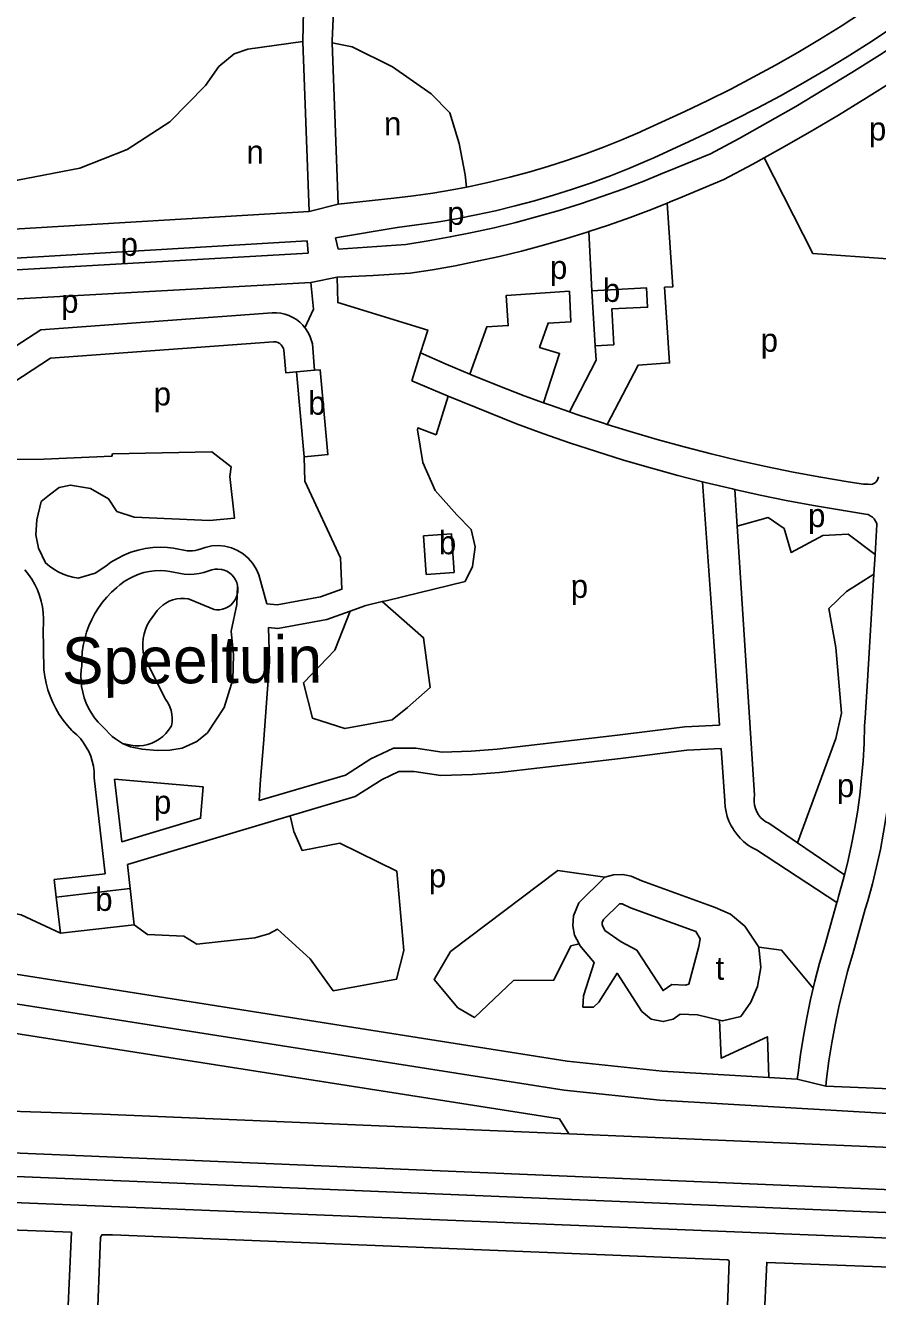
# Model space of a CAD drawing. Extents: x 159675 to 162108, y 386471 to 388472.
# Drawn here: x 160845.9 to 160991.9, y 387458.8 to 387676.6 of the extents above; entities that cross this region are included whole.
import ezdxf

# ---------------------------------------------------------------- set-up
doc = ezdxf.new("R2010")
doc.units = 0
for name, color, linetype in [('BLT_Basislijn', 7, 'Continuous'), ('BLT_Bebouwing', 7, 'Continuous'), ('BLT_Centroide', 7, 'Continuous'), ('BLT_Terrein_beschrifting', 7, 'Continuous'), ('BLT_Vlakafsluiter', 7, 'Continuous')]:
    doc.layers.add(name, color=color, linetype=linetype)

msp = doc.modelspace()

# ---------------------------------------------------------------- linework, layer by layer
at = {"layer": 'BLT_Basislijn'}
for p, q in [((160899.99, 387708.05), (160898.42, 387673.97)), ((160893.42, 387673.78), (160893.42, 387673.82)), ((160894.52, 387644.67), (160893.42, 387673.78)), ((160898.43, 387673.57), (160898.42, 387673.97)), ((160899.48, 387645.93), (160898.43, 387673.57)), ((160951.53, 387658.46), (160956.23, 387660.61)), ((160953.57, 387653.9), (160958.28, 387656.06)), ((160955.88, 387651.55), (160963.26, 387654.57)), ((160957.82, 387646.94), (160965.59, 387650.15)), ((160909.03, 387646.95), (160899.48, 387645.93)), ((160830.99, 387640.9), (160894.52, 387644.67)), ((160909.57, 387641.98), (160899.02, 387640.16)), ((160942.43, 387641.24), (160942.97, 387631.08)), ((160841.25, 387636.5), (160894.17, 387639.64)), ((160894.36, 387637.53), (160894.17, 387639.64)), ((160841.34, 387634.53), (160894.36, 387637.53)), ((160841.56, 387629.54), (160894.81, 387632.55)), ((160895.05, 387622.01), (160895.41, 387617.51)), ((160912.12, 387615.67), (160913.61, 387620.49)), ((160916.29, 387606.43), (160918.32, 387613.05)), ((160963.66, 387573.58), (160961.93, 387598.39)), ((160967.87, 387590.78), (160967.47, 387597.07)), ((160990.31, 387597.97), (160989.52, 387597.97)), ((160970.83, 387544.73), (160967.87, 387590.78)), ((160991.49, 387585.94), (160991.8, 387591.1)), ((160871.24, 387586.99), (160873.6, 387586.57)), ((160991.28, 387582.58), (160991.49, 387585.94)), ((160870.64, 387583.03), (160873.11, 387582.59)), ((160885.88, 387582.47), (160887.23, 387577.49)), ((160990.17, 387564.29), (160991.28, 387582.58)), ((160848.89, 387573.29), (160849.06, 387566.19)), ((160964.83, 387556.68), (160963.66, 387573.58)), ((160866.2, 387568.38), (160869.9, 387561.14)), ((160990.17, 387564.29), (160989.78, 387557.95)), ((160989.78, 387557.95), (160989.69, 387556.53)), ((160965.73, 387543.75), (160965.11, 387552.69)), ((160965.74, 387543.59), (160965.73, 387543.75)), ((160882.07, 387538.41), (160891.22, 387541.14)), ((160973.26, 387539.88), (160978.18, 387536.54)), ((160978.18, 387536.54), (160986.25, 387531.06)), ((160971.17, 387535.33), (160984.94, 387526.34)), ((160863.8, 387528.72), (160863.36, 387532.85)), ((160984.94, 387526.34), (160982.87, 387518.97)), ((160985.02, 387526.61), (160984.94, 387526.34)), ((160989.8, 387525.17), (160987.65, 387517.52)), ((160804.94, 387520.2), (160938.72, 387499.15)), ((160802.17, 387510.51), (160937.41, 387489.24)), ((160973.28, 387496.34), (160978.15, 387496.06)), ((160983.05, 387494.84), (160978.15, 387496.06)), ((161006.33, 387493.92), (160983.05, 387494.84)), ((160859.07, 387490.03), (160939, 387486.67)), ((160937.41, 387489.24), (160939, 387486.67)), ((160939, 387486.67), (161000, 387484.09)), ((160819.56, 387475.92), (160973, 387469.66)), ((160973, 387469.66), (161135.55, 387463.11))]:
    msp.add_line(p, q, dxfattribs=at)
for points in [[(160893.42, 387673.82), (160893.52, 387679.13), (160895.35, 387713.9)], [(160992.97, 387681.26), (160989.35, 387678.83), (160985.68, 387676.46), (160981.98, 387674.16), (160978.23, 387671.93), (160974.43, 387669.77), (160970.61, 387667.68), (160966.74, 387665.66), (160962.84, 387663.71), (160958.9, 387661.84), (160956.23, 387660.61)], [(160994.11, 387675.99), (160990.43, 387673.56), (160986.71, 387671.2), (160982.94, 387668.91), (160979.13, 387666.68), (160975.29, 387664.53), (160971.4, 387662.45), (160967.48, 387660.43), (160963.52, 387658.49), (160959.53, 387656.62), (160958.28, 387656.06)], [(160830.99, 387640.9), (160830.6, 387649.72), (160837.58, 387649.53), (160844.53, 387650.06), (160855.2, 387652.14), (160863.33, 387655.3), (160870.62, 387660.08), (160876.76, 387666.27), (160879.05, 387669.54), (160881.63, 387671.69), (160884, 387672.5), (160893.42, 387673.82)], [(160898.43, 387673.57), (160901.89, 387672.9), (160908.81, 387669.5), (160915.41, 387664.83), (160918.63, 387661.6), (160920.22, 387656.35), (160921.26, 387650.96), (160921.48, 387648.88)], [(160963.26, 387654.57), (160968.18, 387657.21), (160973.07, 387659.93), (160977.92, 387662.71), (160982.73, 387665.57), (160987.5, 387668.49), (160992.22, 387671.48), (160994.36, 387672.86)], [(160972.46, 387653.87), (160975.47, 387655.54), (160980.35, 387658.34), (160985.19, 387661.21), (160989.99, 387664.15), (160994.75, 387667.15), (160995.04, 387667.35)], [(160921.48, 387648.88), (160922.34, 387649.05), (160925.63, 387649.77), (160928.9, 387650.57), (160932.15, 387651.44), (160935.38, 387652.4), (160938.59, 387653.43), (160941.77, 387654.53), (160944.93, 387655.71), (160948.06, 387656.97), (160951.15, 387658.3), (160951.53, 387658.46)], [(160909.57, 387641.98), (160912.97, 387642.39), (160916.37, 387642.88), (160919.75, 387643.45), (160923.11, 387644.1), (160926.46, 387644.83), (160929.79, 387645.64), (160933.11, 387646.52), (160936.4, 387647.48), (160939.66, 387648.51), (160942.91, 387649.62), (160946.12, 387650.81), (160949.31, 387652.08), (160952.46, 387653.41), (160953.57, 387653.9)], [(160965.59, 387650.15), (160970.55, 387652.81), (160972.46, 387653.87)], [(160972.46, 387653.87), (160980.83, 387637.48), (160993.69, 387636.6)], [(160911.08, 387639.05), (160914.88, 387639.65), (160918.67, 387640.33), (160922.43, 387641.08), (160926.19, 387641.92), (160929.92, 387642.83), (160933.64, 387643.82), (160937.33, 387644.89), (160941, 387646.03), (160944.64, 387647.25), (160948.26, 387648.54), (160951.85, 387649.91), (160955.41, 387651.36), (160955.88, 387651.55)], [(160909.03, 387646.95), (160912.37, 387647.36), (160915.71, 387647.84), (160919.03, 387648.41), (160921.48, 387648.88)], [(160942.43, 387641.24), (160945.83, 387642.37), (160949.5, 387643.67), (160953.15, 387645.05), (160955.84, 387646.13)], [(160945.58, 387608.21), (160950.9, 387618.37), (160956.28, 387618.74), (160955.41, 387631.73), (160956.84, 387631.79), (160955.84, 387646.13)], [(160955.84, 387646.13), (160956.76, 387646.5), (160957.82, 387646.94)], [(160911.82, 387634.11), (160915.66, 387634.71), (160919.5, 387635.4), (160923.32, 387636.16), (160927.12, 387637), (160930.9, 387637.92), (160934.67, 387638.92), (160938.41, 387639.99), (160942.13, 387641.14), (160942.43, 387641.24)], [(160911.08, 387639.05), (160899.5, 387638.25), (160899.02, 387640.16)], [(160911.82, 387634.11), (160905.48, 387633.71), (160899.33, 387633.45)], [(160893.76, 387624.79), (160895.23, 387627.97), (160894.81, 387632.55)], [(160913.61, 387620.49), (160914.82, 387624.39), (160899.4, 387629.09), (160899.33, 387633.45)], [(160922.06, 387616.82), (160924.95, 387624.96), (160928.63, 387625.15), (160928.26, 387630.3), (160939.09, 387631.03), (160939.35, 387625.82), (160935.46, 387625.58), (160934, 387621.41), (160937.43, 387620.37), (160934.69, 387611.91)], [(160888.18, 387627.36), (160848.52, 387624.44), (160841.99, 387620.2)], [(160888.18, 387627.36), (160888.91, 387627.36), (160889.64, 387627.27), (160890.35, 387627.11), (160891.04, 387626.86), (160891.7, 387626.55), (160892.32, 387626.17), (160892.9, 387625.71), (160893.42, 387625.2), (160893.76, 387624.79)], [(160893.76, 387624.79), (160893.89, 387624.64), (160894.29, 387624.03), (160894.62, 387623.37), (160894.87, 387622.69), (160895.05, 387622.01)], [(160888.41, 387622.37), (160850.18, 387619.55), (160842.21, 387614.38)], [(160888.41, 387622.37), (160888.78, 387622.34), (160889.13, 387622.24), (160889.46, 387622.07), (160889.73, 387621.83), (160889.95, 387621.53), (160890.1, 387621.2), (160890.15, 387621.02)], [(160890.15, 387621.02), (160890.53, 387617.05), (160892.31, 387617.21)], [(160943.5, 387621.69), (160943.67, 387619.24), (160939.12, 387610.35)], [(160913.61, 387620.49), (160918, 387618.54), (160922.06, 387616.82)], [(160922.06, 387616.82), (160922.42, 387616.67), (160926.86, 387614.86), (160931.34, 387613.14), (160934.69, 387611.91)], [(160912.12, 387615.67), (160918.32, 387613.05)], [(160842.21, 387614.38), (160842.53, 387605.48), (160843.8, 387602.19), (160849.05, 387602.25), (160860.69, 387602.76), (160860.81, 387603.19)], [(160918.32, 387613.05), (160930.02, 387608.3), (160934.57, 387606.64), (160939.14, 387605.05), (160943.74, 387603.55), (160948.36, 387602.11), (160953.01, 387600.76), (160957.68, 387599.48), (160961.93, 387598.39)], [(160934.69, 387611.91), (160935.85, 387611.49), (160939.12, 387610.35)], [(160939.12, 387610.35), (160940.38, 387609.91), (160944.94, 387608.41), (160945.58, 387608.21)], [(160945.58, 387608.21), (160949.52, 387606.99), (160954.12, 387605.64), (160958.75, 387604.37), (160963.4, 387603.18), (160968.07, 387602.06), (160972.75, 387601.02), (160977.45, 387600.06), (160982.17, 387599.18), (160986.9, 387598.38), (160989.52, 387597.97)], [(160907.04, 387577.87), (160907.9, 387578.07), (160921.21, 387581.28), (160922.47, 387583.85), (160922.94, 387587.24), (160922.29, 387590.19), (160919.8, 387592.74), (160916.07, 387596.88), (160914.01, 387601.69), (160913.07, 387607.28), (160913.12, 387607.61), (160916.29, 387606.43)], [(160880.88, 387599.3), (160881.13, 387600.97), (160877.85, 387603.51), (160860.81, 387603.19)], [(160887.23, 387577.49), (160889, 387577.3), (160896.47, 387578.66), (160900.13, 387579.97), (160899.86, 387585.36), (160893.74, 387598.48), (160893.67, 387602.67)], [(160860.11, 387595.47), (160861.56, 387593.3), (160864.51, 387592.35), (160877.43, 387591.77), (160881.72, 387592.18), (160880.88, 387599.3)], [(160992.05, 387599.23), (160991.98, 387598.9), (160991.84, 387598.6), (160991.63, 387598.33), (160991.37, 387598.13), (160991.06, 387597.99), (160990.73, 387597.93), (160990.31, 387597.97)], [(160860.11, 387595.47), (160857.02, 387597.25), (160853.62, 387597.83), (160851.66, 387597.41), (160849.98, 387596.17), (160848.57, 387595.01), (160847.83, 387591.89), (160847.65, 387589.28), (160848.1, 387587.01), (160849.31, 387584.5), (160849.99, 387583.92), (160850.73, 387583.4), (160851.5, 387582.95), (160852.32, 387582.57), (160853.16, 387582.26), (160854.03, 387582.03), (160854.92, 387581.88)], [(160961.93, 387598.39), (160962.37, 387598.28), (160967.07, 387597.16), (160967.47, 387597.07)], [(160967.47, 387597.07), (160971.8, 387596.11), (160976.54, 387595.15), (160981.3, 387594.26), (160986.07, 387593.45), (160989.85, 387592.87)], [(160989.85, 387592.87), (160990.28, 387592.76), (160990.67, 387592.58), (160991.03, 387592.33), (160991.34, 387592.02), (160991.58, 387591.66), (160991.76, 387591.26), (160991.8, 387591.1)], [(160991.49, 387585.94), (160986.88, 387589.4), (160982.53, 387589.17), (160977.1, 387586.3), (160975.92, 387590.36), (160973.19, 387592.26), (160967.87, 387590.78)], [(160854.92, 387581.88), (160857.82, 387582.73), (160859.66, 387583.93), (160860.54, 387584.59), (160861.63, 387585.26), (160862.77, 387585.84), (160863.95, 387586.31), (160865.17, 387586.69), (160866.42, 387586.96), (160867.69, 387587.12), (160868.96, 387587.17), (160870.22, 387587.11), (160871.24, 387586.99)], [(160873.6, 387586.57), (160874.04, 387586.54), (160874.51, 387586.55), (160874.98, 387586.61), (160875.43, 387586.71), (160876.01, 387586.89)], [(160876.01, 387586.89), (160876.7, 387587.15), (160877.81, 387587.39), (160878.94, 387587.45), (160880.07, 387587.35), (160880.51, 387587.24)], [(160880.51, 387587.24), (160881.17, 387587.07), (160882.22, 387586.63), (160883.19, 387586.04), (160884.06, 387585.32), (160884.81, 387584.46), (160885.42, 387583.5), (160885.88, 387582.47)], [(160845.75, 387583.32), (160846.39, 387582.53), (160846.97, 387581.69), (160847.48, 387580.8), (160847.92, 387579.88), (160848.28, 387578.93), (160848.57, 387577.96), (160848.79, 387576.96), (160848.92, 387575.95)], [(160862.05, 387580.72), (160862.8, 387581.28), (160863.59, 387581.77), (160864.42, 387582.19), (160865.29, 387582.54), (160866.18, 387582.82), (160867.1, 387583.01), (160868.02, 387583.13), (160868.95, 387583.17), (160869.89, 387583.13), (160870.64, 387583.03)], [(160873.11, 387582.59), (160873.96, 387582.53), (160874.81, 387582.56), (160875.65, 387582.66), (160876.48, 387582.84), (160877.33, 387583.12)], [(160877.33, 387583.12), (160877.83, 387583.3), (160878.35, 387583.41), (160878.87, 387583.44), (160879.4, 387583.39), (160879.54, 387583.36)], [(160879.54, 387583.36), (160879.91, 387583.27), (160880.4, 387583.06), (160880.85, 387582.79), (160881.25, 387582.45), (160881.6, 387582.05), (160881.89, 387581.61), (160882.1, 387581.12), (160882.24, 387580.61), (160882.3, 387580.09), (160882.28, 387579.56), (160882.18, 387579.04), (160882.01, 387578.54), (160881.76, 387578.08), (160881.44, 387577.65), (160881.06, 387577.28), (160880.64, 387576.98), (160880.17, 387576.73), (160879.66, 387576.57), (160879.14, 387576.48), (160878.62, 387576.47), (160878.24, 387576.51)], [(160985.74, 387558.76), (160984.78, 387569.99), (160983.54, 387576.67), (160986.57, 387579.62), (160991.28, 387582.58)], [(160855.52, 387566.84), (160855.53, 387568.01), (160855.62, 387569.18), (160855.79, 387570.33), (160856.04, 387571.48), (160856.37, 387572.6), (160856.77, 387573.7), (160857.25, 387574.77), (160857.8, 387575.8), (160858.41, 387576.8), (160859.1, 387577.74), (160859.85, 387578.65), (160860.65, 387579.49), (160861.52, 387580.28), (160862.05, 387580.72)], [(160882.24, 387580.61), (160882.11, 387577.36), (160881.16, 387572.79), (160881.52, 387568.73), (160881.41, 387564.49), (160879.91, 387559.7)], [(160873.78, 387578.32), (160873.12, 387578.4), (160872.46, 387578.4), (160871.8, 387578.32), (160871.15, 387578.16), (160870.53, 387577.93), (160869.95, 387577.62), (160869.4, 387577.24), (160868.9, 387576.81), (160868.46, 387576.31), (160868.08, 387575.76)], [(160878.24, 387576.51), (160874.2, 387578.16), (160873.78, 387578.32)], [(160907.04, 387577.87), (160914.1, 387571.66), (160915.25, 387563.16), (160911.38, 387559.73), (160908.75, 387557.63), (160900.63, 387556.14), (160895.1, 387557.89), (160893.54, 387563.96), (160898.89, 387569.56), (160901.53, 387576.22)], [(160901.53, 387576.22), (160904.24, 387577.19), (160907.04, 387577.87)], [(160848.92, 387575.95), (160848.97, 387574.93), (160848.95, 387573.91), (160848.89, 387573.29)], [(160868.08, 387575.76), (160867.57, 387575.16), (160867.13, 387574.51), (160866.75, 387573.81), (160866.45, 387573.08), (160866.21, 387572.32), (160866.06, 387571.55), (160865.99, 387570.76), (160865.99, 387570.15)], [(160887.54, 387573.44), (160889.15, 387573.26), (160897.51, 387574.78), (160901.53, 387576.22)], [(160887.54, 387573.44), (160887.68, 387567.57), (160886.68, 387553.5), (160886.18, 387547.38), (160885.94, 387543.81)], [(160865.99, 387570.15), (160866, 387569.97), (160866.08, 387569.18), (160866.2, 387568.38)], [(160859.74, 387555.85), (160859.01, 387556.5), (160858.34, 387557.2), (160857.72, 387557.96), (160857.18, 387558.76), (160856.7, 387559.61), (160856.29, 387560.49), (160855.95, 387561.4), (160855.69, 387562.34), (160855.51, 387563.29), (160855.41, 387564.26), (160855.38, 387565.23), (160855.44, 387566.2), (160855.52, 387566.84)], [(160849.06, 387566.19), (160849.2, 387565.03), (160849.43, 387563.88), (160849.73, 387562.75), (160850.1, 387561.65), (160850.56, 387560.57), (160851.08, 387559.53), (160851.68, 387558.52), (160852.34, 387557.56), (160853.06, 387556.64), (160853.85, 387555.78), (160854.02, 387555.61)], [(160870.89, 387556.6), (160871, 387557.25), (160871.03, 387557.91), (160870.98, 387558.57), (160870.84, 387559.22), (160870.64, 387559.84), (160870.35, 387560.44), (160870, 387561), (160869.9, 387561.14)], [(160862.54, 387553.56), (160863.87, 387553.01), (160865.88, 387552.57), (160868.45, 387552.35), (160870.61, 387552.4), (160872.74, 387552.73), (160875.23, 387553.87), (160877.07, 387555.38), (160879.91, 387559.7)], [(160978.18, 387536.54), (160984.75, 387554.43), (160985.74, 387558.76)], [(160854.02, 387555.61), (160854.68, 387555.03), (160855.29, 387554.39), (160855.83, 387553.69), (160856.31, 387552.95), (160856.73, 387552.17), (160857.07, 387551.36), (160857.33, 387550.52), (160857.52, 387549.65), (160857.63, 387548.78), (160857.66, 387547.89), (160857.65, 387547.68)], [(160859.74, 387555.85), (160860.2, 387555.29), (160860.72, 387554.78), (160861.29, 387554.33), (160862.54, 387553.56)], [(160862.54, 387553.56), (160863.96, 387553.24), (160864.69, 387553.16), (160865.42, 387553.15), (160866.14, 387553.23), (160866.85, 387553.39), (160867.54, 387553.62), (160868.2, 387553.93), (160868.82, 387554.3), (160869.4, 387554.75), (160869.92, 387555.25), (160870.39, 387555.81), (160870.79, 387556.42), (160870.89, 387556.6)], [(160885.94, 387543.81), (160900.72, 387548.14), (160905.07, 387550.91), (160908.98, 387552.73), (160912.78, 387552.73), (160917.29, 387552.07), (160922.29, 387552.26), (160926.75, 387552.57), (160947.36, 387554.96), (160958.87, 387556.42), (160964.83, 387556.68)], [(160989.69, 387556.53), (160989.6, 387553.57), (160989.43, 387550.61), (160989.18, 387547.66), (160988.85, 387544.72), (160988.45, 387541.78), (160987.96, 387538.86), (160987.4, 387535.95), (160986.75, 387533.06), (160986.25, 387531.06)], [(160891.22, 387541.14), (160902.39, 387544.46), (160907, 387547.39), (160909.87, 387548.73), (160912.49, 387548.73), (160917.07, 387548.06), (160922.5, 387548.27), (160927.12, 387548.58), (160947.84, 387550.99), (160959.21, 387552.43), (160965.11, 387552.69)], [(160857.65, 387547.68), (160859.52, 387531.24), (160850.83, 387530.24), (160851.16, 387527.24)], [(160970.83, 387544.73), (160970.75, 387544.15), (160970.74, 387543.56), (160970.82, 387542.97), (160970.97, 387542.41), (160971.2, 387541.86), (160971.5, 387541.36), (160971.87, 387540.9), (160972.29, 387540.49), (160972.77, 387540.14), (160973.26, 387539.88)], [(160965.74, 387543.59), (160965.8, 387542.73), (160965.94, 387541.87), (160966.16, 387541.04), (160966.45, 387540.23), (160966.82, 387539.44), (160967.14, 387538.91)], [(160993.73, 387543.52), (160993.44, 387541.37), (160992.95, 387538.38), (160992.39, 387535.4), (160991.74, 387532.44), (160991.02, 387529.5), (160990.22, 387526.58), (160989.8, 387525.17)], [(160864.53, 387522.51), (160866.79, 387520.84), (160873.02, 387520.52), (160875.26, 387519.2), (160885.21, 387520.26), (160887.57, 387520.93), (160889.09, 387521.72), (160894.68, 387516.68), (160898.64, 387511.19), (160909.48, 387513.16), (160910.7, 387518.07), (160909.5, 387531.67), (160899.75, 387536.45), (160893.28, 387535.25), (160891.86, 387538.45), (160891.22, 387541.14)], [(160882.07, 387538.41), (160863.36, 387532.85)], [(160967.14, 387538.91), (160967.26, 387538.7), (160967.77, 387538), (160968.34, 387537.35), (160968.96, 387536.76), (160969.64, 387536.22), (160970.37, 387535.75), (160971.17, 387535.33)], [(160945.16, 387530.66), (160937.13, 387531.78), (160918.71, 387517.9), (160915.94, 387513.13), (160919.98, 387508.29), (160922.84, 387506.62), (160929.51, 387512.93), (160936.45, 387513.01), (160939.35, 387518.89), (160940.76, 387519.21)], [(160940.76, 387519.21), (160939.98, 387520.71), (160939.67, 387522.3), (160939.82, 387524.05), (160940.74, 387526.25), (160945.16, 387530.66)], [(160945.16, 387530.66), (160946.64, 387531.05), (160948.28, 387531.13), (160949.7, 387530.85), (160951.5, 387530.01), (160964.08, 387525.45), (160966.73, 387524.29), (160969.14, 387522.26), (160971.59, 387518.68)], [(160986.25, 387531.06), (160986.03, 387530.19), (160985.23, 387527.34), (160985.02, 387526.61)], [(160837.66, 387525.12), (160840.06, 387525.2), (160845.17, 387524.22), (160851.89, 387521.04)], [(160947.66, 387526.1), (160944.97, 387523.41), (160944.74, 387522.86), (160944.71, 387522.57), (160944.75, 387522.37), (160945.19, 387521.52), (160947.95, 387519.56), (160950.65, 387518.13)], [(160961.53, 387520.07), (160960.77, 387521.33), (160949.58, 387525.39), (160948.14, 387526.06), (160947.91, 387526.11), (160947.66, 387526.1)], [(160796.88, 387520.81), (160797.21, 387519.52), (160797.71, 387518.45), (160798.36, 387517.56), (160799.14, 387516.86), (160799.91, 387516.29), (160801.35, 387515.71), (160938.19, 387494.18)], [(160964.85, 387506.14), (160961.03, 387507.08), (160958.11, 387507.18), (160956.9, 387506.35), (160955.19, 387505.9), (160953.14, 387506.34), (160951.52, 387507.64), (160947.26, 387514.18), (160944.12, 387509.24), (160943.21, 387508.39), (160941.41, 387508.4), (160941.54, 387510.33), (160943.37, 387516.06), (160940.9, 387518.93), (160940.76, 387519.21)], [(160959.55, 387512.33), (160961.27, 387518.75), (160961.53, 387520.07)], [(160971.59, 387518.68), (160971.89, 387515.17), (160971.32, 387511.93), (160970.22, 387509.25), (160968.46, 387506.76), (160965.32, 387506.03), (160964.85, 387506.14)], [(160980.88, 387511.62), (160975.46, 387518.12), (160971.59, 387518.68)], [(160982.87, 387518.97), (160981.98, 387515.9), (160981.17, 387512.81), (160980.88, 387511.62)], [(160950.65, 387518.13), (160955.15, 387511.22), (160956.65, 387512.24), (160959, 387512.15), (160959.55, 387512.33)], [(160987.65, 387517.52), (160986.78, 387514.51), (160985.99, 387511.48), (160985.27, 387508.43), (160984.63, 387505.37), (160984.07, 387502.29), (160983.59, 387499.19), (160983.19, 387496.09), (160983.05, 387494.84)], [(160980.88, 387511.62), (160980.43, 387509.7), (160979.77, 387506.58), (160979.2, 387503.43), (160978.7, 387500.28), (160978.28, 387497.11), (160978.15, 387496.06)], [(160964.85, 387506.14), (160965.11, 387499.67), (160973.05, 387503.31), (160973.28, 387496.34)], [(160938.72, 387499.15), (160954.99, 387497.41), (160973.28, 387496.34)], [(160803.86, 387493.99), (160819.17, 387491.47), (160830.88, 387490.99), (160859.07, 387490.03)], [(160938.19, 387494.18), (160954.58, 387492.43), (161036.63, 387487.64)], [(160805.42, 387483.12), (160823.16, 387484.27), (161243.1, 387466.63)], [(160805.42, 387483.12), (160806.11, 387479.2), (160827.71, 387480.06), (161242.88, 387462.85)], [(160851.75, 387425.91), (160853.75, 387469.82), (160814.47, 387471.31), (160806.86, 387460.5), (160806.89, 387459.24), (160831.28, 387303.64), (160871.26, 387301.66)], [(160964.92, 387427.96), (160958.51, 387428.42), (160958.36, 387432.05), (160857.49, 387436.46), (160858.72, 387468.91), (160858.95, 387469.37), (160860.79, 387469.4), (160966.24, 387465.08), (160966.46, 387464.92), (160966.27, 387458.63), (160964.92, 387427.96)], [(160972.4, 387453.77), (160972.92, 387464.66), (161040.72, 387462.07)]]:
    msp.add_lwpolyline(points, dxfattribs=at)
msp.add_lwpolyline([(160876.33, 387546.14), (160861.17, 387547.42), (160862.39, 387536.73), (160875.9, 387540.75)], close=True, dxfattribs=at)
at = {"layer": 'BLT_Bebouwing'}
for p, q in [((160943.5, 387621.69), (160942.97, 387631.08)), ((160946.73, 387621.88), (160943.5, 387621.69)), ((160892.31, 387617.21), (160895.41, 387617.51)), ((160893.67, 387602.67), (160892.31, 387617.21)), ((160896.6, 387602.94), (160893.67, 387602.67)), ((160914.54, 387582.49), (160914.08, 387589.12)), ((160919.38, 387582.83), (160914.54, 387582.49)), ((160851.16, 387527.24), (160859.86, 387528.26)), ((160859.86, 387528.26), (160863.8, 387528.72)), ((160863.8, 387528.72), (160864.53, 387522.51)), ((160851.89, 387521.04), (160851.16, 387527.24)), ((160864.53, 387522.51), (160851.89, 387521.04))]:
    msp.add_line(p, q, dxfattribs=at)
for points in [[(160942.97, 387631.08), (160952.33, 387631.59), (160952.5, 387628.29), (160946.39, 387628.02), (160946.73, 387621.88)], [(160895.41, 387617.51), (160896.37, 387617.59), (160897.73, 387603.05), (160896.6, 387602.94)], [(160914.08, 387589.12), (160918.92, 387589.45), (160919.38, 387582.83)]]:
    msp.add_lwpolyline(points, dxfattribs=at)
at = {"layer": 'BLT_Vlakafsluiter'}
for p, q in [((160899.48, 387645.93), (160894.52, 387644.67)), ((160899.33, 387633.45), (160894.81, 387632.55))]:
    msp.add_line(p, q, dxfattribs=at)

# ---------------------------------------------------------------- texts
at = {"layer": 'BLT_Centroide'}
for s, p in [('n', (160907.33, 387657.76)), ('p', (160990.43, 387656.87)), ('n', (160883.75, 387652.9)), ('p', (160918.15, 387642.41)), ('p', (160862.18, 387637.09)), ('p', (160935.77, 387633.14)), ('b', (160944.85, 387629.21)), ('p', (160852, 387627.34)), ('p', (160971.88, 387620.67)), ('p', (160867.86, 387611.47)), ('b', (160894.35, 387609.89)), ('p', (160980, 387590.64)), ('b', (160916.73, 387585.98)), ('p', (160939.33, 387578.5)), ('p', (160984.95, 387544.37)), ('p', (160867.9, 387541.53)), ('p', (160915.02, 387528.92)), ('b', (160857.84, 387524.88)), ('t', (160964.15, 387513.07))]:
    msp.add_text(s, height=4, dxfattribs=at).set_placement(p)
at = {"layer": 'BLT_Terrein_beschrifting'}
msp.add_text('Speeltuin', height=8, rotation=0.3414, dxfattribs=at).set_placement((160852.14, 387563.74))

doc.saveas('drawing.dxf')
